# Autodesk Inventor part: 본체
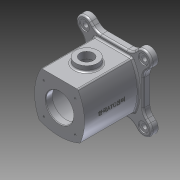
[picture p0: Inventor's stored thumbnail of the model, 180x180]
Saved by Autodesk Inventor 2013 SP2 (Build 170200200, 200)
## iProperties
Created: 2022-01
Part Number: 본체
Material: 알루미늄 6061
Document SubType Name: Modeling
Designer: aa
Density: 2.71 g/cm^3
Mass: 1225.62 g
Surface Area: 915.501 cm^2
Volume: 452.257 cm^3
Author: aa
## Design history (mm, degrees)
sketch "스케치1"
  geometry: L1 (32.942, 45)-(-32.942, 45); L2 (-45, -45)-(45, 45); L3 (45, -45)-(-45, 45); A1 r 90 centre (-45, 0) between (37.029, -37.029) and (32.942, 45); A2 r 90 centre (0, 45) between (-37.029, -37.029) and (37.029, -37.029); A3 r 90 centre (45, 0) between (-32.942, 45) and (-37.029, -37.029); 6 further points
  constraints: 7 point on circle, 6 end point, 5 midpoint, 3 centre point, 3 horizontal alignment, 3 vertical alignment, 1 coincident
  dimensions: "d4" = 90 distance of L3.end L2.end; "d5" = 90 distance of L2.end L3.start; "d49" = 90 radius of A1; "d50" = 90 radius of A2; "d51" = 90 radius of A3; "d52" = 65.88457 distance of L1.start L1.end; "d53" = 74.05881 distance of A1.start A2.start; "d54" = 90 distance of A3.centre A1.centre; "d55" = 90 horizontal distance of L2.start L2.end; "d56" = 90 horizontal distance of L3.start L3.end; "d57" = 45 distance of A2.centre L2.end
extrude "돌출1" new body sketch "스케치1" stored distance "d7" = 110; taper "d8" = 0 deg
sketch "스케치2"
  geometry: L1 (0, 55)-(0, -55); L2 (25, 43)-(37, 43); L3 (37, 43)-(37, -43); L4 (37, -43)-(25, -43); L5 (45, 55)-(-37.029, 55) reference; L6 (-37.029, -55)-(45, -55) reference; L7 (45, -55)-(45, 55) reference; L8 (25, 43)-(25, 55); L9 (25, -43)-(25, -55); L10 (25, 55)-(0, 55); L11 (25, -55)-(0, -55); 3 further points
  constraints: 16 end point, 3 perpendicular, 2 coincident, 2 point on line, 1 midpoint
  dimensions: "d10" = 110 distance of L1.start L1.end; "d12" = 86 distance of L2.end L3.end; "d13" = 74 diameter of L3 L1; "d58" = 12 distance of L2.start L8.end; "d59" = 12 distance of L4.end L9.end; "d60" = 50 diameter of L8 L1; "d61" = 50 diameter of L9 L1
revolve "회전1" sketch "스케치2" stored, may be unused: angle "d16" = 90 deg
node "작업 평면1"
sketch "스케치3"
  geometry: L1 (32.942, -55)-(-32.942, -55) reference; C1 r 20 at (0, 6); 3 further points
  constraints: 1 centre point, 1 vertical alignment
  dimensions: "d18" = 40 diameter of C1; "d19" = 61 distance from line of C1.centre L1
extrude "돌출2" join sketch "스케치3" stored distance "d20" = 110; taper "d21" = 0 deg
sketch "스케치4"
  geometry: C1 r 20 at (0, 0) reference; C2 r 12 at (0, 0); 1 further point
  constraints: 1 centre point, 1 coincident
  dimensions: "d22" = 24 diameter of C2
extrude "돌출3" cut sketch "스케치4" distance "d23" = 13; taper "d24" = 0 deg
sketch "스케치6"
  geometry: L1 (32.942, 45)-(-32.942, 45) reference; L2 (-53, -53)-(53, -53); L3 (53, -53)-(53, 53); L4 (53, 53)-(-53, 53); L5 (-53, 53)-(-53, -53); L6 (-53, -53)-(53, 53); L7 (53, -53)-(-53, 53); L8 (-63.607, 42.393)-(-53, 31.787); L9 (-42.393, 63.607)-(-31.787, 53); L10 (42.393, 63.607)-(31.787, 53); L11 (63.607, 42.393)-(53, 31.787); L12 (-63.607, -42.393)-(-53, -31.787); L13 (-42.393, -63.607)-(-31.787, -53); L14 (63.607, -42.393)-(53, -31.787); L15 (42.393, -63.607)-(31.787, -53); L16 (-45, -45)-(45, 45); L17 (45, -45)-(-45, 45); C1 r 25 at (0, 0) reference; C2 r 25 at (0, 0); A1 r 15 centre (-53, 53) between (-42.393, 63.607) and (-63.607, 42.393); A2 r 15 centre (-53, -53) between (-63.607, -42.393) and (-42.393, -63.607); A3 r 15 centre (53, -53) between (42.393, -63.607) and (63.607, -42.393); A4 r 15 centre (53, 53) between (63.607, 42.393) and (42.393, 63.607); A5 r 90 centre (0, 45) between (-37.029, -37.029) and (37.029, -37.029) reference; A6 r 90 centre (-45, 0) between (37.029, -37.029) and (32.942, 45) reference; 8 further points
  constraints: 32 end point, 10 midpoint, 8 parallel, 8 point on circle, 8 point on line, 8 tangent, 5 centre point, 5 coincident, 3 perpendicular, 2 horizontal alignment, 2 vertical alignment, 1 concentric, 1 horizontal
  dimensions: "d28" = 106 distance of L4.end L3.end; "d29" = 106 distance of L3.end L2.end; "d36" = 30 distance between parallel lines of L9 L8; "d39" = 30 diameter of A3; "d40" = 30 distance between parallel lines of L11 L10; "d41" = 30 distance between parallel lines of L13 L12; "d62" = 90 distance of L17.end L16.end; "d63" = 90 distance of L16.end L17.start; "d64" = 90 horizontal distance of L17.start L17.end; "d65" = 90 horizontal distance of L16.start L16.end; "d66" = 98 distance from line of L2 A5.centre; "d67" = 98 distance from line of L3 A6.centre
extrude "돌출5" join sketch "스케치6" distance "d34" = 12; taper "d35" = 0 deg
sketch "스케치8"
  geometry: L1 (0, 0)-(28.284, 28.284); L2 (0, 0)-(40, 0); C1 r 25 at (0, 0) reference; 1 further point
  constraints: 4 end point, 1 coincident, 1 equal length, 1 horizontal
  dimensions: "d69" = 40 distance of L1.start L1.end; "d70" = 45 deg angle of L2 L1
hole "구멍2" sketch "스케치8" at (28.284, 28.284) diameter "d71" = 3.242; stored, may be unused: countersink angle "d75" = 90 deg, drill point angle "d77" = 118 deg; dims "d72" = 9, "d73" = 4, "d74" = 2, "d76" = 11
fillet "모깎기1" dims "d81" = 20
fillet "모깎기2" dims "d82" = 3
fillet "모깎기3" dims "d83" = 3
chamfer "모따기1" distance "d84" = 1; stored, may be unused: second distance "d85" = 2, angle "d86" = 45 deg
node "작업 평면2"
sketch "스케치9"
  geometry: L1 (43.448, 55)-(-35.954, 55) reference; L2 (23.503, -55)-(-23.503, -55) reference; L3 (55, 26)-(55, -14) reference; 2 further points
  constraints: 1 other
  dimensions: "d89" = 61 distance from line of L2 point (0, 6); "d90" = 55 distance from line of point (0, 6) L3
feature "엠보싱1" sketch "스케치9" dims "d5" = 90, "d91" = 0.5, "d92" = 0
sketch "스케치10"
  geometry: A1 r 12 centre (-53, 53) between (-44.515, 61.485) and (-61.485, 44.515) reference; A2 r 12 centre (-53, -53) between (-61.485, -44.515) and (-44.515, -61.485) reference; A3 r 12 centre (53, -53) between (44.515, -61.485) and (61.485, -44.515) reference; A4 r 12 centre (53, 53) between (61.485, 44.515) and (44.515, 61.485) reference; 5 further points
  constraints: 4 coincident
hole "구멍3" sketch "스케치10" at (-53, 53), (-53, -53), (53, -53), (53, 53) diameter "d93" = 9; stored, may be unused: countersink angle "d97" = 90 deg, drill point angle "d99" = 118 deg; dims "d94" = 9, "d95" = 18, "d96" = 2, "d98" = 11
node "작업 평면3"
sketch "스케치11"
  geometry: C1 r 15 at (0, 0); 1 further point
  constraints: 1 centre point
  dimensions: "d101" = 30 diameter of C1
extrude "돌출6" cut sketch "스케치11" stored distance "d102" = 10; taper "d103" = 0 deg
chamfer "모따기2" distance "d104" = 1; stored, may be unused: second distance "d105" = 2, angle "d106" = 45 deg
fillet "모깎기4" dims "d107" = 3
node "솔리드1"
pattern_circular "원형 패턴1" dims angle "d79" = 360 deg
mirror "대칭1"
other parameters: "d17" = 55, "d100" = -13
